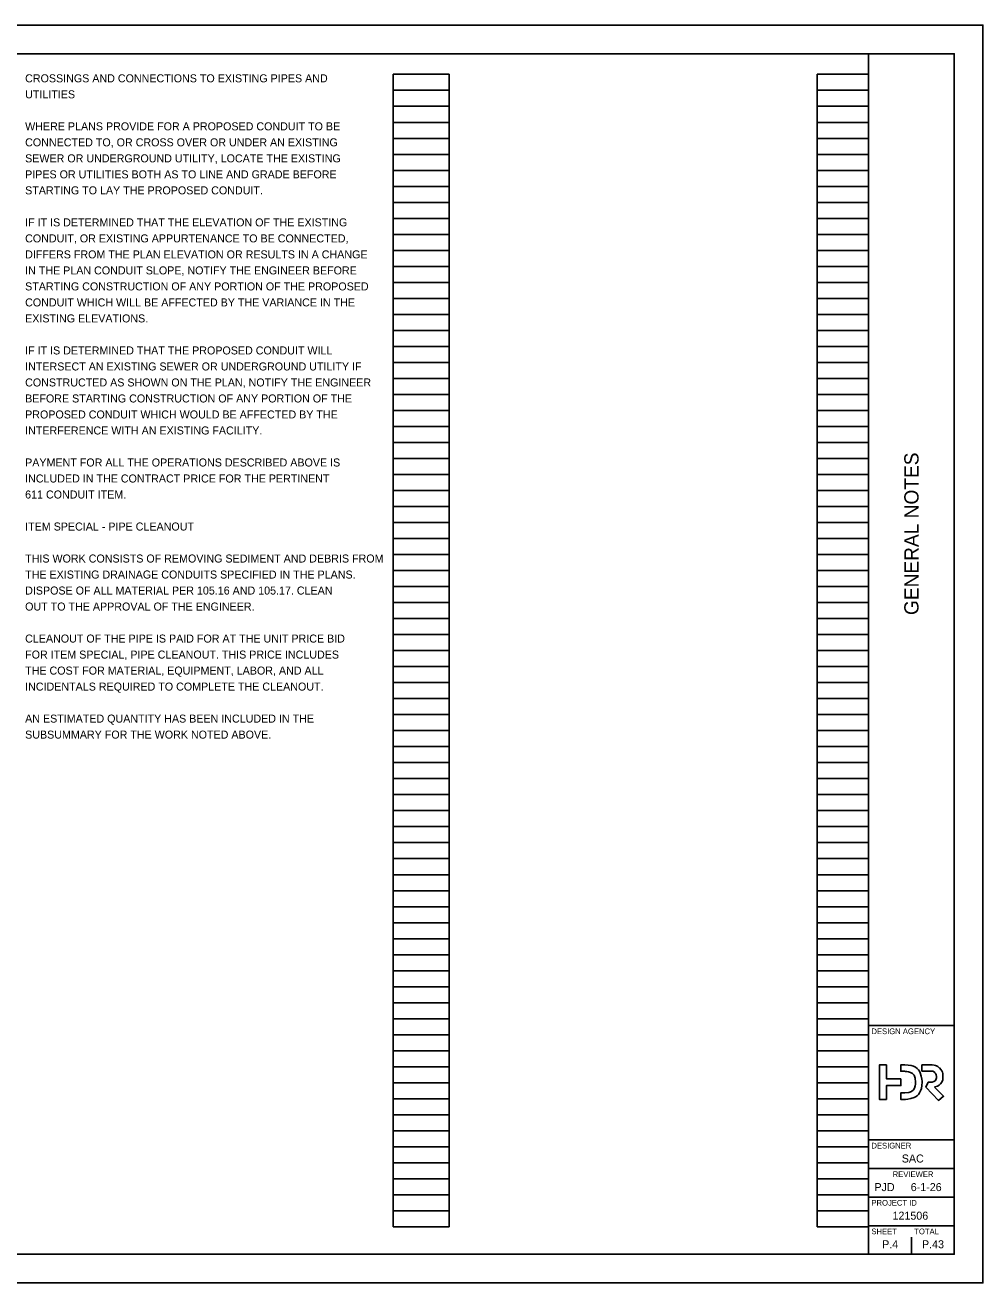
# Model space of a CAD drawing. Extents: x 0 to 34, y 0 to 22.
# Drawn here: x 17.24 to 34, y 0 to 22 of the extents above; entities that cross this region are included whole.
import ezdxf

# ---------------------------------------------------------------- set-up
doc = ezdxf.new("R2010")
doc.units = 0
for name, color, linetype in [('SH_Border', 7, 'Continuous'), ('SH_Cut_Line', 7, 'Continuous'), ('SH_Data', 7, 'Continuous'), ('SH_Text', 7, 'Continuous')]:
    doc.layers.add(name, color=color, linetype=linetype)

msp = doc.modelspace()

# ---------------------------------------------------------------- linework, layer by layer
at = {"layer": 'SH_Border'}
for p, q in [((32, 0.5), (32, 21.5)), ((32, 4.5), (33.5, 4.5)), ((32, 2.5), (33.5, 2.5)), ((32, 2), (33.5, 2)), ((32, 1.5), (33.5, 1.5)), ((32, 1), (33.5, 1))]:
    msp.add_line(p, q, dxfattribs=at)
msp.add_lwpolyline([(1.5, 21.5), (33.5, 21.5), (33.5, 0.5), (1.5, 0.5)], close=True, dxfattribs=at)
at = {"layer": 'SH_Cut_Line'}
msp.add_lwpolyline([(0, 0), (34, 0), (34, 22), (0, 22)], close=True, dxfattribs=at)
at = {"layer": 'SH_Data'}
for p, q in [((23.68, 0.98), (23.68, 21.14)), ((23.68, 21.14), (24.66, 21.14)), ((24.66, 0.98), (24.66, 21.14)), ((31.1, 0.98), (31.1, 21.14)), ((31.1, 21.14), (32, 21.14)), ((32, 0.98), (32, 21.14)), ((23.68, 20.86), (24.66, 20.86)), ((31.1, 20.86), (32, 20.86)), ((23.68, 20.58), (24.66, 20.58)), ((31.1, 20.58), (32, 20.58)), ((23.68, 20.3), (24.66, 20.3)), ((31.1, 20.3), (32, 20.3)), ((23.68, 20.02), (24.66, 20.02)), ((31.1, 20.02), (32, 20.02)), ((23.68, 19.74), (24.66, 19.74)), ((31.1, 19.74), (32, 19.74)), ((23.68, 19.46), (24.66, 19.46)), ((31.1, 19.46), (32, 19.46)), ((23.68, 19.18), (24.66, 19.18)), ((31.1, 19.18), (32, 19.18)), ((23.68, 18.9), (24.66, 18.9)), ((31.1, 18.9), (32, 18.9)), ((23.68, 18.62), (24.66, 18.62)), ((31.1, 18.62), (32, 18.62)), ((23.68, 18.34), (24.66, 18.34)), ((31.1, 18.34), (32, 18.34)), ((23.68, 18.06), (24.66, 18.06)), ((31.1, 18.06), (32, 18.06)), ((23.68, 17.78), (24.66, 17.78)), ((31.1, 17.78), (32, 17.78)), ((23.68, 17.5), (24.66, 17.5)), ((31.1, 17.5), (32, 17.5)), ((23.68, 17.22), (24.66, 17.22)), ((31.1, 17.22), (32, 17.22)), ((23.68, 16.94), (24.66, 16.94)), ((31.1, 16.94), (32, 16.94)), ((23.68, 16.66), (24.66, 16.66)), ((31.1, 16.66), (32, 16.66)), ((23.68, 16.38), (24.66, 16.38)), ((31.1, 16.38), (32, 16.38)), ((23.68, 16.1), (24.66, 16.1)), ((31.1, 16.1), (32, 16.1)), ((23.68, 15.82), (24.66, 15.82)), ((31.1, 15.82), (32, 15.82)), ((23.68, 15.54), (24.66, 15.54)), ((31.1, 15.54), (32, 15.54)), ((23.68, 15.26), (24.66, 15.26)), ((31.1, 15.26), (32, 15.26)), ((23.68, 14.98), (24.66, 14.98)), ((31.1, 14.98), (32, 14.98)), ((23.68, 14.7), (24.66, 14.7)), ((31.1, 14.7), (32, 14.7)), ((23.68, 14.42), (24.66, 14.42)), ((31.1, 14.42), (32, 14.42)), ((23.68, 14.14), (24.66, 14.14)), ((31.1, 14.14), (32, 14.14)), ((23.68, 13.86), (24.66, 13.86)), ((31.1, 13.86), (32, 13.86)), ((23.68, 13.58), (24.66, 13.58)), ((31.1, 13.58), (32, 13.58)), ((23.68, 13.3), (24.66, 13.3)), ((31.1, 13.3), (32, 13.3)), ((23.68, 13.02), (24.66, 13.02)), ((31.1, 13.02), (32, 13.02)), ((23.68, 12.74), (24.66, 12.74)), ((31.1, 12.74), (32, 12.74)), ((23.68, 12.46), (24.66, 12.46)), ((31.1, 12.46), (32, 12.46)), ((23.68, 12.18), (24.66, 12.18)), ((31.1, 12.18), (32, 12.18)), ((23.68, 11.9), (24.66, 11.9)), ((31.1, 11.9), (32, 11.9)), ((23.68, 11.62), (24.66, 11.62)), ((31.1, 11.62), (32, 11.62)), ((23.68, 11.34), (24.66, 11.34)), ((31.1, 11.34), (32, 11.34)), ((23.68, 11.06), (24.66, 11.06)), ((31.1, 11.06), (32, 11.06)), ((23.68, 10.78), (24.66, 10.78)), ((31.1, 10.78), (32, 10.78)), ((23.68, 10.5), (24.66, 10.5)), ((31.1, 10.5), (32, 10.5)), ((23.68, 10.22), (24.66, 10.22)), ((31.1, 10.22), (32, 10.22)), ((23.68, 9.94), (24.66, 9.94)), ((31.1, 9.94), (32, 9.94)), ((23.68, 9.66), (24.66, 9.66)), ((31.1, 9.66), (32, 9.66)), ((23.68, 9.38), (24.66, 9.38)), ((31.1, 9.38), (32, 9.38)), ((23.68, 9.1), (24.66, 9.1)), ((31.1, 9.1), (32, 9.1)), ((23.68, 8.82), (24.66, 8.82)), ((31.1, 8.82), (32, 8.82)), ((23.68, 8.54), (24.66, 8.54)), ((31.1, 8.54), (32, 8.54)), ((23.68, 8.26), (24.66, 8.26)), ((31.1, 8.26), (32, 8.26)), ((23.68, 7.98), (24.66, 7.98)), ((31.1, 7.98), (32, 7.98)), ((23.68, 7.7), (24.66, 7.7)), ((31.1, 7.7), (32, 7.7)), ((23.68, 7.42), (24.66, 7.42)), ((31.1, 7.42), (32, 7.42)), ((23.68, 7.14), (24.66, 7.14)), ((31.1, 7.14), (32, 7.14)), ((23.68, 6.86), (24.66, 6.86)), ((31.1, 6.86), (32, 6.86)), ((23.68, 6.58), (24.66, 6.58)), ((31.1, 6.58), (32, 6.58)), ((23.68, 6.3), (24.66, 6.3)), ((31.1, 6.3), (32, 6.3)), ((23.68, 6.02), (24.66, 6.02)), ((31.1, 6.02), (32, 6.02)), ((23.68, 5.74), (24.66, 5.74)), ((31.1, 5.74), (32, 5.74)), ((23.68, 5.46), (24.66, 5.46)), ((31.1, 5.46), (32, 5.46)), ((23.68, 5.18), (24.66, 5.18)), ((31.1, 5.18), (32, 5.18)), ((23.68, 4.9), (24.66, 4.9)), ((31.1, 4.9), (32, 4.9)), ((23.68, 4.62), (24.66, 4.62)), ((31.1, 4.62), (32, 4.62)), ((23.68, 4.34), (24.66, 4.34)), ((31.1, 4.34), (32, 4.34)), ((23.68, 4.06), (24.66, 4.06)), ((31.1, 4.06), (32, 4.06)), ((23.68, 3.78), (24.66, 3.78)), ((31.1, 3.78), (32, 3.78)), ((23.68, 3.5), (24.66, 3.5)), ((31.1, 3.5), (32, 3.5)), ((32.75, 3.5), (32.75, 3.5)), ((23.68, 3.22), (24.66, 3.22)), ((31.1, 3.22), (32, 3.22)), ((23.68, 2.94), (24.66, 2.94)), ((31.1, 2.94), (32, 2.94)), ((23.68, 2.66), (24.66, 2.66)), ((31.1, 2.66), (32, 2.66)), ((23.68, 2.38), (24.66, 2.38)), ((31.1, 2.38), (32, 2.38)), ((23.68, 2.1), (24.66, 2.1)), ((31.1, 2.1), (32, 2.1)), ((23.68, 1.82), (24.66, 1.82)), ((31.1, 1.82), (32, 1.82)), ((23.68, 1.54), (24.66, 1.54)), ((31.1, 1.54), (32, 1.54)), ((23.68, 1.26), (24.66, 1.26)), ((31.1, 1.26), (32, 1.26)), ((23.68, 0.98), (24.66, 0.98)), ((31.1, 0.98), (32, 0.98)), ((32.375, 0.675), (32.375, 0.675)), ((32.75, 0.5), (32.75, 0.8))]:
    msp.add_line(p, q, dxfattribs=at)
msp.add_lwpolyline([(32.565, 3.571), (32.311, 3.571), (32.311, 3.813), (32.189, 3.813), (32.189, 3.209), (32.311, 3.209), (32.311, 3.451), (32.565, 3.451)], close=True, dxfattribs=at)
for points in [[(32.634, 3.813), (32.562, 3.813), (32.562, 3.7), (32.634, 3.7)], [(33.063, 3.813), (32.935, 3.813), (32.935, 3.704), (33.072, 3.704)], [(32.634, 3.322), (32.562, 3.322), (32.562, 3.209), (32.634, 3.209)], [(32.936, 3.511), (32.936, 3.511), (32.936, 3.511), (32.936, 3.512), (32.936, 3.512)], [(33.077, 3.51), (33.043, 3.51), (33.003, 3.424), (33.226, 3.192), (33.313, 3.265), (33.155, 3.425)]]:
    msp.add_lwpolyline(points, dxfattribs=at)
for points in [[(32.936, 3.512), (32.936, 3.512), (32.935, 3.686), (32.808, 3.813), (32.634, 3.813)], [(33.239, 3.759), (33.239, 3.759), (33.193, 3.802), (33.141, 3.813), (33.063, 3.813)], [(33.302, 3.605), (33.302, 3.605), (33.302, 3.668), (33.284, 3.716), (33.239, 3.759)], [(32.634, 3.7), (32.634, 3.7), (32.744, 3.7), (32.822, 3.622), (32.822, 3.511)], [(33.072, 3.704), (33.072, 3.704), (33.113, 3.704), (33.141, 3.696), (33.161, 3.676)], [(33.189, 3.607), (33.189, 3.607), (33.189, 3.546), (33.136, 3.51), (33.077, 3.51)], [(33.155, 3.425), (33.155, 3.425), (33.242, 3.441), (33.302, 3.521), (33.302, 3.605)], [(33.161, 3.676), (33.161, 3.676), (33.179, 3.658), (33.189, 3.634), (33.189, 3.607)], [(32.822, 3.511), (32.822, 3.511), (32.822, 3.4), (32.744, 3.322), (32.634, 3.322)], [(32.634, 3.209), (32.634, 3.209), (32.808, 3.209), (32.935, 3.336), (32.936, 3.511)]]:
    msp.add_open_spline(points, degree=3, dxfattribs=at)

# ---------------------------------------------------------------- texts
msp.add_text('GENERAL NOTES', height=0.25, rotation=90, dxfattribs=at).set_placement((32.875, 11.682))
for s, height, p in [('DESIGN AGENCY', 0.1, (32.05, 4.35)), ('DESIGNER', 0.1, (32.05, 2.35)), ('SAC', 0.14, (32.581, 2.105)), ('REVIEWER', 0.1, (32.422, 1.85)), ('PJD', 0.14, (32.103, 1.605)), ('6-1-26', 0.14, (32.738, 1.605)), ('PROJECT ID', 0.1, (32.05, 1.35)), ('121506', 0.14, (32.419, 1.105)), ('SHEET', 0.1, (32.05, 0.85)), ('TOTAL', 0.1, (32.8, 0.85)), ('P.4', 0.14, (32.237, 0.605)), ('P.43', 0.14, (32.935, 0.605))]:
    msp.add_text(s, height=height, dxfattribs=at).set_placement(p)
at = {"layer": 'SH_Text'}
for s, p in [('CROSSINGS AND CONNECTIONS TO EXISTING PIPES AND', (17.24, 21)), ('UTILITIES', (17.24, 20.72)), ('WHERE PLANS PROVIDE FOR A PROPOSED CONDUIT TO BE', (17.24, 20.16)), ('CONNECTED TO, OR CROSS OVER OR UNDER AN EXISTING', (17.24, 19.88)), ('SEWER OR UNDERGROUND UTILITY, LOCATE THE EXISTING', (17.24, 19.6)), ('PIPES OR UTILITIES BOTH AS TO LINE AND GRADE BEFORE', (17.24, 19.32)), ('STARTING TO LAY THE PROPOSED CONDUIT.', (17.24, 19.04)), ('IF IT IS DETERMINED THAT THE ELEVATION OF THE EXISTING', (17.24, 18.48)), ('CONDUIT, OR EXISTING APPURTENANCE TO BE CONNECTED,', (17.24, 18.2)), ('DIFFERS FROM THE PLAN ELEVATION OR RESULTS IN A CHANGE', (17.24, 17.92)), ('IN THE PLAN CONDUIT SLOPE, NOTIFY THE ENGINEER BEFORE', (17.24, 17.64)), ('STARTING CONSTRUCTION OF ANY PORTION OF THE PROPOSED', (17.24, 17.36)), ('CONDUIT WHICH WILL BE AFFECTED BY THE VARIANCE IN THE', (17.24, 17.08)), ('EXISTING ELEVATIONS.', (17.24, 16.8)), ('IF IT IS DETERMINED THAT THE PROPOSED CONDUIT WILL', (17.24, 16.24)), ('INTERSECT AN EXISTING SEWER OR UNDERGROUND UTILITY IF', (17.24, 15.96)), ('CONSTRUCTED AS SHOWN ON THE PLAN, NOTIFY THE ENGINEER', (17.24, 15.68)), ('BEFORE STARTING CONSTRUCTION OF ANY PORTION OF THE', (17.24, 15.4)), ('PROPOSED CONDUIT WHICH WOULD BE AFFECTED BY THE', (17.24, 15.12)), ('INTERFERENCE WITH AN EXISTING FACILITY.', (17.24, 14.84)), ('PAYMENT FOR ALL THE OPERATIONS DESCRIBED ABOVE IS', (17.24, 14.28)), ('INCLUDED IN THE CONTRACT PRICE FOR THE PERTINENT', (17.24, 14)), ('611 CONDUIT ITEM.', (17.24, 13.72)), ('ITEM SPECIAL - PIPE CLEANOUT', (17.24, 13.16)), ('THIS WORK CONSISTS OF REMOVING SEDIMENT AND DEBRIS FROM', (17.24, 12.6)), ('THE EXISTING DRAINAGE CONDUITS SPECIFIED IN THE PLANS.', (17.24, 12.32)), ('DISPOSE OF ALL MATERIAL PER 105.16 AND 105.17. CLEAN', (17.24, 12.04)), ('OUT TO THE APPROVAL OF THE ENGINEER.', (17.24, 11.76)), ('CLEANOUT OF THE PIPE IS PAID FOR AT THE UNIT PRICE BID', (17.24, 11.2)), ('FOR ITEM SPECIAL, PIPE CLEANOUT. THIS PRICE INCLUDES', (17.24, 10.92)), ('THE COST FOR MATERIAL, EQUIPMENT, LABOR, AND ALL', (17.24, 10.64)), ('INCIDENTALS REQUIRED TO COMPLETE THE CLEANOUT.', (17.24, 10.36)), ('AN ESTIMATED QUANTITY HAS BEEN INCLUDED IN THE', (17.24, 9.8)), ('SUBSUMMARY FOR THE WORK NOTED ABOVE.', (17.24, 9.52))]:
    msp.add_text(s, height=0.14, dxfattribs=at).set_placement(p)

doc.saveas('drawing.dxf')
